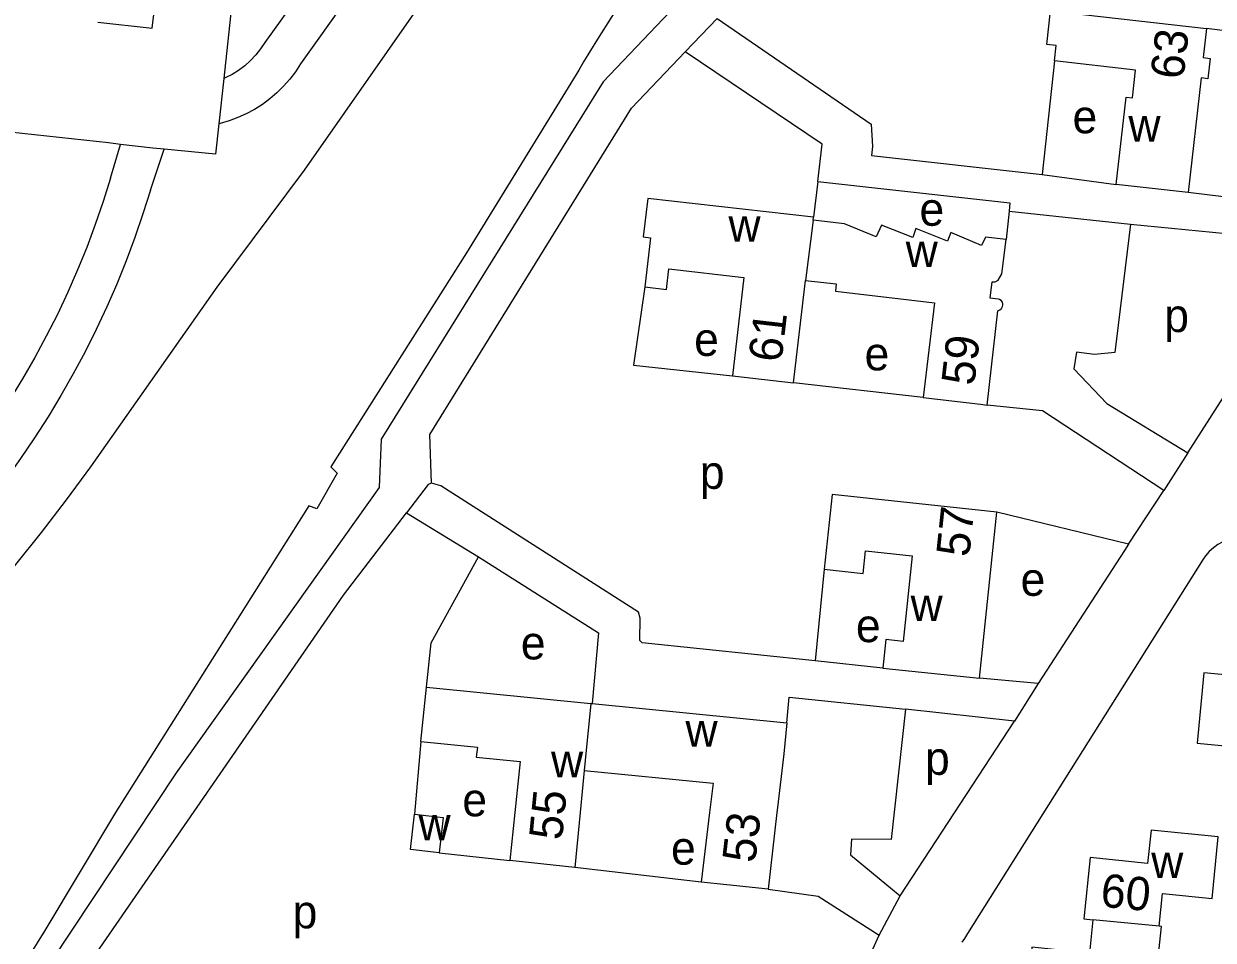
# Model space of a CAD drawing. Extents: x 161936 to 163647, y 386450 to 388633.
# Drawn here: x 162807.2 to 162950.3, y 386984.7 to 387094.9 of the extents above; entities that cross this region are included whole.
import ezdxf

# ---------------------------------------------------------------- set-up
doc = ezdxf.new("R2010")
doc.units = 0
for name, color, linetype in [('BLT_Basislijn', 7, 'Continuous'), ('BLT_Bebouwing', 7, 'Continuous'), ('BLT_Centroide', 7, 'Continuous'), ('BLT_Huisnummer', 7, 'Continuous'), ('BLT_Onderverdeling_panden', 7, 'Continuous')]:
    doc.layers.add(name, color=color, linetype=linetype)

msp = doc.modelspace()

# ---------------------------------------------------------------- linework, layer by layer
at = {"layer": 'BLT_Basislijn'}
for p, q in [((162844.07, 387205.6), (162831.26, 387088.34)), ((162921.12, 387203.12), (162840.48, 387090.09)), ((162876.3, 387148.95), (162836.2, 387092.67)), ((162886.8, 387091.53), (162890.63, 387095.54)), ((162931.24, 387090.45), (162929.76, 387076.8)), ((162874.01, 387089.34), (162860.48, 387067.36)), ((162831.26, 387088.34), (162830.66, 387082.89)), ((162830.66, 387082.89), (162830.26, 387079.23)), ((162817.37, 387080.59), (162798.61, 387082.64)), ((162818.82, 387080.41), (162817.37, 387080.59)), ((162817.63, 387076.35), (162818.82, 387080.41)), ((162822.72, 387079.94), (162818.82, 387080.41)), ((162822.42, 387074.92), (162824.07, 387079.82)), ((162824.07, 387079.82), (162822.72, 387079.94)), ((162830.26, 387079.23), (162824.07, 387079.82)), ((162902.76, 387075.96), (162902.24, 387071.64)), ((162929.76, 387076.8), (162938.66, 387075.6)), ((162965.63, 387072.39), (162947.33, 387074.62)), ((162925.77, 387072.37), (162925.41, 387068.96)), ((162925.77, 387072.37), (162940.39, 387070.82)), ((162940.39, 387070.82), (162963.2, 387068.58)), ((162830.43, 387063.22), (162815.21, 387041.61)), ((162915.45, 387049.95), (162899.82, 387051.7)), ((162947.27, 387043.29), (162944.4, 387038.78)), ((162940.16, 387032.3), (162944.4, 387038.78)), ((162853.25, 387036.08), (162861.91, 387030.77)), ((162940.16, 387032.3), (162924.32, 387036.17)), ((162949.15, 387030.52), (162920.76, 386985.44)), ((162903.52, 387029.28), (162902.43, 387018.26)), ((162910.59, 387017.4), (162902.43, 387018.26)), ((162929.27, 387015.53), (162922.21, 387016.17)), ((162929.27, 387015.53), (162926.42, 387011.01)), ((162926.42, 387011.01), (162913.29, 387012.45)), ((162912.66, 386990.01), (162926.42, 387011.01)), ((162854.99, 387008.57), (162854.21, 386999.81)), ((162857.2, 386995.18), (162865.68, 386994.24)), ((162888.72, 386991.65), (162873.49, 386993.4)), ((162910.12, 386985.26), (162912.66, 386990.01)), ((162906.15, 386976.47), (162910.12, 386985.26)), ((162920.39, 386984.86), (162920.08, 386984.41)), ((162920.76, 386985.44), (162920.39, 386984.86))]:
    msp.add_line(p, q, dxfattribs=at)
for points in [[(162994.68, 387190.62), (162985.54, 387189.48), (162980.86, 387188.14), (162974.88, 387184.86), (162966.28, 387177.45), (162938.28, 387149.79), (162903.24, 387114.51), (162892.82, 387104.85), (162888.74, 387100), (162884.14, 387095.5), (162876.92, 387087.93), (162850.19, 387044.96), (162849.96, 387039.13), (162825.52, 387004.78), (162807.9, 386978.22), (162790.61, 386951.66), (162774.68, 386925.41), (162767.27, 386912.48), (162763.63, 386897.48)], [(162816.08, 387095.12), (162822.65, 387094.38), (162823.34, 387100), (162831.5, 387171.05)], [(162894.1, 387152.3), (162872.5, 387122.42), (162855.79, 387098.55), (162840.95, 387077.32), (162830.43, 387063.22)], [(162896.36, 387118.1), (162894.07, 387115.83), (162891.84, 387113.51), (162889.67, 387111.13), (162887.57, 387108.7), (162885.52, 387106.22), (162883.53, 387103.68), (162881.61, 387101.1), (162879.75, 387098.48), (162877.96, 387095.8), (162876.23, 387093.09), (162874.57, 387090.33), (162874.01, 387089.34)], [(162966.43, 387098.51), (162958.87, 387094.74), (162955.23, 387093.9), (162953.36, 387093.89), (162949.52, 387094.37)], [(162890.63, 387095.54), (162909.17, 387082.84), (162909.34, 387080.16), (162909.2, 387079.08), (162929.76, 387076.8)], [(162836.2, 387092.67), (162835.68, 387091.89), (162835.11, 387091.17), (162834.47, 387090.49), (162833.78, 387089.88), (162833.04, 387089.32), (162832.25, 387088.83), (162831.42, 387088.41), (162831.26, 387088.34)], [(162856.25, 387039.65), (162856.04, 387045.52), (162880.33, 387084.75), (162886.8, 387091.53)], [(162902.76, 387075.96), (162903.29, 387080.42), (162886.8, 387091.53)], [(162840.48, 387090.09), (162839.87, 387089.15), (162839.19, 387088.26), (162838.45, 387087.41), (162837.65, 387086.62), (162836.8, 387085.89), (162835.9, 387085.22), (162834.95, 387084.62), (162833.97, 387084.09), (162832.94, 387083.63), (162831.89, 387083.24), (162830.81, 387082.93), (162830.66, 387082.89)], [(162817.63, 387076.35), (162816.75, 387073.55), (162815.79, 387070.77), (162814.76, 387068.02), (162813.66, 387065.3), (162812.48, 387062.61), (162811.23, 387059.96), (162809.9, 387057.34), (162808.51, 387054.75), (162807.05, 387052.21), (162805.51, 387049.7), (162803.91, 387047.24), (162802.25, 387044.83), (162800.51, 387042.45), (162798.72, 387040.13), (162796.86, 387037.86), (162794.94, 387035.64), (162792.96, 387033.47), (162790.92, 387031.36), (162790.5, 387030.93)], [(162902.76, 387075.96), (162925.87, 387073.36), (162925.77, 387072.37)], [(162822.42, 387074.92), (162821.52, 387072.05), (162820.55, 387069.21), (162819.49, 387066.4), (162818.37, 387063.61), (162817.17, 387060.86), (162815.9, 387058.14), (162814.56, 387055.45), (162813.15, 387052.8), (162811.66, 387050.19), (162810.11, 387047.62), (162808.49, 387045.09), (162806.8, 387042.61), (162805.05, 387040.17), (162803.23, 387037.78), (162801.35, 387035.43), (162799.41, 387033.15), (162797.4, 387030.91), (162795.34, 387028.72), (162794.03, 387027.39)], [(162940.39, 387070.82), (162938.49, 387055.35), (162936.06, 387055.14), (162933.9, 387055.4), (162933.58, 387053.39), (162937.53, 387049.24), (162947.27, 387043.29)], [(162947.27, 387043.29), (162961.45, 387065.41), (162963.2, 387068.58)], [(162860.48, 387067.36), (162844.14, 387041.61), (162844.89, 387040.86), (162842.45, 387036.54), (162841.51, 387036.91), (162818.24, 387000), (162809.72, 386985.81), (162799.34, 386969.19)], [(162881.94, 387063.27), (162880.59, 387053.83), (162892.47, 387052.56)], [(162944.4, 387038.78), (162929.8, 387048.33), (162923.12, 387049.05)], [(162815.21, 387041.61), (162812.27, 387037.65), (162809.26, 387033.73), (162806.18, 387029.86), (162803.05, 387026.05), (162799.85, 387022.28), (162796.59, 387018.57), (162793.27, 387014.91), (162789.9, 387011.31), (162786.46, 387007.76), (162782.97, 387004.26), (162781.97, 387003.28)], [(162856.25, 387039.65), (162855.84, 387039.48), (162853.25, 387036.08)], [(162902.43, 387018.26), (162881.6, 387020.45), (162881.33, 387020.7), (162881.39, 387023.42), (162881.16, 387024.11), (162857.39, 387039.32), (162856.25, 387039.65)], [(162813.2, 386979.16), (162845.68, 387026.17), (162853.25, 387036.08)], [(162956.73, 387032.46), (162956.12, 387032.75), (162955.47, 387032.97), (162954.81, 387033.1), (162954.14, 387033.16), (162953.46, 387033.14), (162952.79, 387033.03), (162952.14, 387032.85), (162951.51, 387032.6), (162950.91, 387032.27), (162950.36, 387031.88), (162949.86, 387031.42), (162949.42, 387030.9), (162949.15, 387030.52)], [(162940.16, 387032.3), (162939.66, 387031.54), (162929.27, 387015.53)], [(162855.64, 387015.11), (162856.23, 387020.42), (162861.91, 387030.77)], [(162861.91, 387030.77), (162876.35, 387021.62), (162875.6, 387013.13)], [(162899.01, 387010.81), (162899.3, 387013.89), (162913.29, 387012.45)], [(162913.29, 387012.45), (162911.57, 386996.77), (162906.81, 386996.82), (162906.7, 386994.92), (162912.66, 386990.01)], [(162896.76, 386990.79), (162902.78, 386989.95), (162910.12, 386985.26)]]:
    msp.add_lwpolyline(points, dxfattribs=at)
at = {"layer": 'BLT_Bebouwing'}
for p, q in [((162947.33, 387074.62), (162938.66, 387075.6)), ((162902.2, 387071.29), (162902.24, 387071.64)), ((162899.82, 387051.7), (162901.26, 387064.05)), ((162923.12, 387049.05), (162924.44, 387060.4)), ((162925.03, 387061.05), (162925.04, 387061.21)), ((162892.47, 387052.56), (162899.82, 387051.7)), ((162922.21, 387016.17), (162924.32, 387036.17)), ((162910.59, 387017.4), (162922.21, 387016.17)), ((162854.99, 387008.57), (162855.64, 387015.11)), ((162855.64, 387015.11), (162875.44, 387013.15)), ((162875.44, 387013.15), (162875.6, 387013.13)), ((162875.6, 387013.13), (162899.01, 387010.81)), ((162873.49, 386993.4), (162865.68, 386994.24))]:
    msp.add_line(p, q, dxfattribs=at)
for points in [[(162931.24, 387090.45), (162931.45, 387092.3), (162930.31, 387092.43), (162930.77, 387096.49), (162949.52, 387094.37)], [(162949.52, 387094.37), (162949.12, 387090.86), (162949.98, 387090.76), (162949.71, 387088.3), (162948.89, 387088.4), (162947.33, 387074.62)], [(162938.66, 387075.6), (162939.85, 387086.11), (162940.63, 387086.02), (162941.01, 387089.35), (162931.24, 387090.45)], [(162902.24, 387071.64), (162882.28, 387073.89), (162881.74, 387069.28), (162882.62, 387069.17), (162881.94, 387063.27)], [(162925.41, 387068.96), (162922.92, 387069.25), (162922.46, 387068.26), (162918.76, 387069.81), (162918.38, 387068.76), (162914.55, 387070.27), (162914.18, 387069.2), (162910.42, 387070.68), (162909.78, 387069.3), (162905.95, 387070.85), (162902.2, 387071.29)], [(162924.48, 387061.8), (162923.49, 387061.92), (162923.72, 387063.88), (162924.11, 387063.88), (162924.45, 387064.09), (162924.91, 387064.84), (162925.41, 387068.96)], [(162881.94, 387063.27), (162884.53, 387062.96), (162884.82, 387065.45), (162893.85, 387064.4), (162892.47, 387052.56)], [(162901.26, 387064.05), (162904.97, 387063.62), (162904.87, 387062.75), (162916.78, 387061.36), (162915.45, 387049.95)], [(162925.04, 387061.21), (162924.97, 387061.43), (162924.83, 387061.62), (162924.63, 387061.76), (162924.48, 387061.8)], [(162924.44, 387060.4), (162924.67, 387060.5), (162924.86, 387060.67), (162924.99, 387060.89), (162925.03, 387061.05)], [(162915.45, 387049.95), (162922.33, 387049.14), (162923.12, 387049.05)], [(162924.32, 387036.17), (162904.47, 387038.27), (162903.52, 387029.28)], [(162903.52, 387029.28), (162908.21, 387028.78), (162908.5, 387031.51), (162914.12, 387030.92), (162913.02, 387020.61), (162910.95, 387020.83), (162910.59, 387017.4)], [(162962.69, 387018.49), (162962.74, 387019.11), (162955.1, 387019.83), (162954.77, 387016.29), (162949.22, 387016.81), (162948.43, 387008.35), (162958.47, 387007.41), (162958.55, 387008.27), (162961.08, 387008.03), (162961.69, 387013.8), (162962.39, 387013.74), (162962.24, 387012.12), (162967.44, 387011.63), (162968.04, 387017.99), (162962.69, 387018.49)], [(162899.01, 387010.81), (162898.65, 387007.07), (162897.9, 387000.62), (162897.83, 387000.03), (162896.76, 386990.79)], [(162854.99, 387008.57), (162861.78, 387007.9), (162861.65, 387006.68), (162866.94, 387006.15), (162866.29, 387000), (162865.68, 386994.24)], [(162874.65, 387005.08), (162874.14, 387000), (162873.49, 386993.4)], [(162874.65, 387005.08), (162890.15, 387003.54), (162889.73, 387000), (162888.72, 386991.65)], [(162857.2, 386995.18), (162853.73, 386995.57), (162854.21, 386999.81)], [(162854.21, 386999.81), (162857.68, 386999.42), (162857.2, 386995.18)], [(162943.84, 386986.34), (162944.24, 386990.27), (162950.2, 386989.66), (162950.96, 386997.09), (162942.86, 386997.91), (162942.45, 386993.9), (162935.54, 386994.6), (162934.79, 386987.23), (162935.86, 386987.12)], [(162896.76, 386990.79), (162891.79, 386991.32), (162888.72, 386991.65)], [(162935.86, 386987.12), (162935.45, 386983.11), (162928.53, 386983.82), (162927.78, 386976.55)], [(162937, 386975.61), (162937.39, 386979.37), (162943.33, 386978.76), (162944.11, 386986.32), (162943.84, 386986.34)]]:
    msp.add_lwpolyline(points, dxfattribs=at)
at = {"layer": 'BLT_Onderverdeling_panden'}
for p, q in [((162902.2, 387071.29), (162901.26, 387064.05)), ((162875.44, 387013.15), (162874.65, 387005.08)), ((162943.84, 386986.34), (162935.86, 386987.12))]:
    msp.add_line(p, q, dxfattribs=at)

# ---------------------------------------------------------------- texts
at = {"layer": 'BLT_Centroide'}
for s, p in [('e', (162933.41, 387081.75)), ('w', (162940.14, 387080.75)), ('e', (162914.99, 387070.62)), ('w', (162892, 387068.7)), ('w', (162913.33, 387065.64)), ('p', (162944.45, 387057.83)), ('e', (162887.87, 387054.96)), ('e', (162908.38, 387053.22)), ('p', (162888.56, 387038.96)), ('e', (162927.16, 387026.09)), ('w', (162913.92, 387023.05)), ('e', (162907.34, 387020.52)), ('e', (162867.01, 387018.44)), ('w', (162886.83, 387007.95)), ('w', (162870.65, 387004.25)), ('p', (162915.66, 387004.55)), ('e', (162859.97, 386999.56)), ('w', (162854.69, 386996.65)), ('e', (162885.09, 386993.74)), ('w', (162942.88, 386992.12)), ('p', (162839.54, 386986.08))]:
    msp.add_text(s, height=4, dxfattribs=at).set_placement(p)
at = {"layer": 'BLT_Huisnummer'}
for s, rotation, p in [('63', 83.5535, (162946.75, 387088.14)), ('61', 83.3529, (162898.37, 387054.1)), ('59', 83.3945, (162921.58, 387051.3)), ('57', 83.9725, (162920.97, 387030.68)), ('55', 84.3607, (162871.96, 386996.61)), ('53', 83.3672, (162895.21, 386993.87)), ('60', 354.4621, (162936.68, 386988.71))]:
    msp.add_text(s, height=4, rotation=rotation, dxfattribs=at).set_placement(p)

doc.saveas('drawing.dxf')
